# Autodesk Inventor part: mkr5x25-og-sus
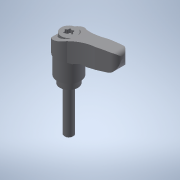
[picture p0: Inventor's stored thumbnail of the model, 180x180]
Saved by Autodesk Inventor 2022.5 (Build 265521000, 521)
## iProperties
Created: 2017-09
Part Number: mkr5x25-og-sus
Material: 一般
Document SubType Name: Modeling
Designer: imaocorp
Density: 1 g/cm^3
Appearance: 既定
Author: imaocorp
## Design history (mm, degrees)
node "mkr5x25-og-sus.x_t1"
node "mkr5x25-og-sus"
node "Base1"
